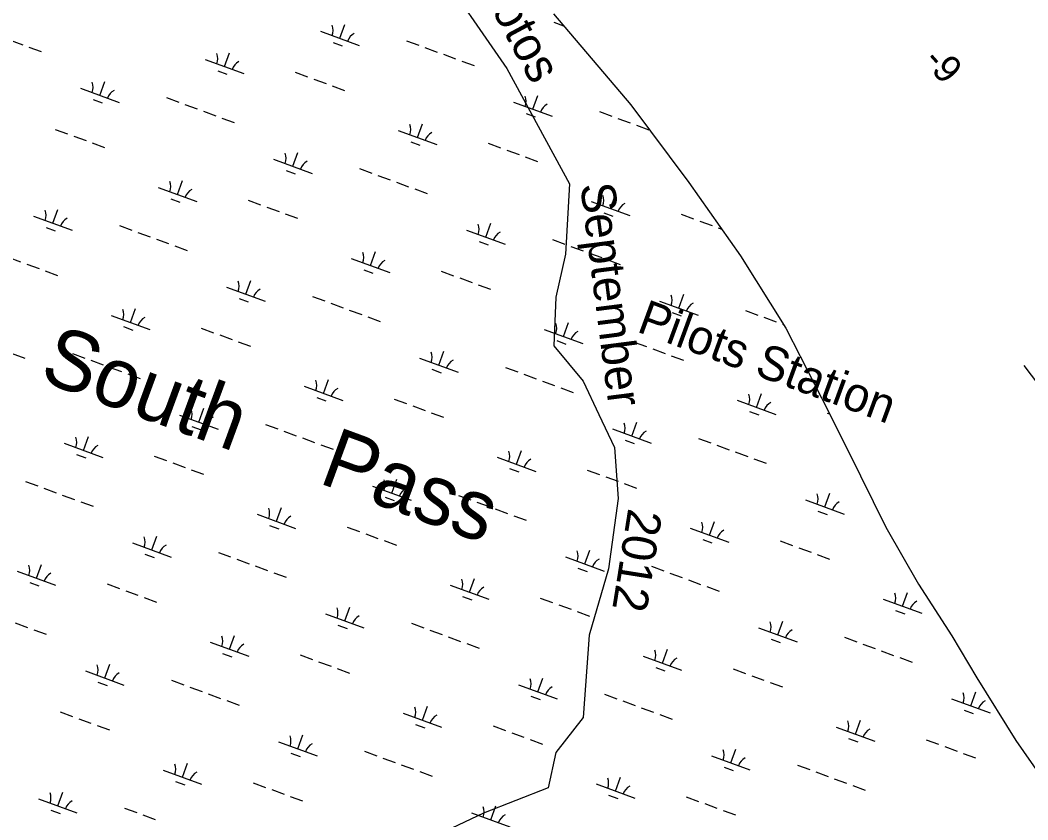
# Model space of a CAD drawing. Extents: x 3972907 to 3994831, y 172639 to 190852.
# Drawn here: x 3980022 to 3981252, y 185903 to 186879 of the extents above; entities that cross this region are included whole.
import ezdxf

# ---------------------------------------------------------------- set-up
doc = ezdxf.new("R2010")
doc.units = 0
for name, color, linetype in [('V-BLDG-IDEN', 7, 'Continuous'), ('V-RIVR-EDGE', 7, 'Continuous'), ('V-RIVR-IDEN', 7, 'Continuous'), ('V-RIVR-JETY', 7, 'Continuous'), ('V-RIVR-RANG', 7, 'Continuous'), ('V-WETL-SWMP', 7, 'Continuous')]:
    doc.layers.add(name, color=color, linetype=linetype)

msp = doc.modelspace()

# ---------------------------------------------------------------- linework, layer by layer
at = {"layer": 'V-RIVR-EDGE'}
msp.add_lwpolyline([(3980525.8, 186951.6), (3980616.4, 186820.4), (3980692.8, 186679.6), (3980688, 186593.7), (3980676.1, 186541.2), (3980673.7, 186481.6), (3980709.5, 186438.6), (3980728.6, 186398.1), (3980747.7, 186357.5), (3980752.4, 186295.5), (3980740.5, 186209.6), (3980716.7, 186128.5), (3980709.5, 186028.3), (3980676.1, 185985.3), (3980666.6, 185942.4), (3980587.8, 185911.3), (3980501.9, 185870.8), (3980444.7, 185844.5), (3980363.5, 185765.8), (3980299.1, 185684.7), (3980222.8, 185605.9), (3980072.4, 185567.8), (3979962.7, 185546.3)], dxfattribs=at)
at = {"layer": 'V-RIVR-JETY'}
msp.add_lwpolyline([(3981247.3, 186457.7), (3981342, 186332.9)], dxfattribs=at)
msp.add_spline([(3980663.7, 188142.5), (3980923.3, 187897.8), (3981219.1, 187593.7), (3981381.5, 187411.2), (3981548.8, 187223.5), (3981746, 186997.4), (3981995.9, 186703.1), (3982288, 186350.3), (3982495.8, 186079.5), (3982762.8, 185654.7), (3982971, 185292.4), (3983111.2, 185037.5), (3983200, 184881.8), (3983229.9, 184826.4)], degree=3, dxfattribs=at)
at = {"layer": 'V-WETL-SWMP'}
for p, q in [((3980412.6, 186857.1), (3980418.8, 186874)), ((3980673.7, 186876.8), (3980685.7, 186872.4)), ((3980389.1, 186865.7), (3980436, 186848.5)), ((3980010.4, 186854.7), (3980025.5, 186849.2)), ((3980404.3, 186851.9), (3980415.5, 186847.8)), ((3980493.9, 186854.2), (3980508.9, 186848.7)), ((3980033, 186846.4), (3980048, 186840.9)), ((3980271.8, 186822.6), (3980278, 186839.5)), ((3980516.4, 186845.9), (3980531.4, 186840.4)), ((3980538.9, 186837.7), (3980553.9, 186832.1)), ((3980248.3, 186831.2), (3980295.2, 186814)), ((3980561.4, 186829.4), (3980576.5, 186823.9)), ((3980263.5, 186817.4), (3980274.8, 186813.3)), ((3980358.2, 186815.6), (3980373.2, 186810)), ((3980119.6, 186787.5), (3980125.8, 186804.4)), ((3980380.7, 186807.3), (3980395.7, 186801.8)), ((3980096.2, 186796.2), (3980143.1, 186778.9)), ((3980403.3, 186799), (3980418.3, 186793.5)), ((3980648.1, 186770.5), (3980654.3, 186787.4)), ((3980111.3, 186782.4), (3980122.6, 186778.2)), ((3980200.9, 186784.7), (3980215.9, 186779.2)), ((3980223.5, 186776.4), (3980238.5, 186770.9)), ((3980624.6, 186779.1), (3980671.6, 186761.9)), ((3980246, 186768.1), (3980261, 186762.6)), ((3980639.8, 186765.3), (3980651.1, 186761.2)), ((3980729.4, 186767.6), (3980744.4, 186762.1)), ((3980268.5, 186759.8), (3980283.5, 186754.3)), ((3980507.3, 186736), (3980513.5, 186752.9)), ((3980751.9, 186759.4), (3980767, 186753.9)), ((3980774.5, 186751.1), (3980789.5, 186745.6)), ((3980065.3, 186746), (3980080.3, 186740.5)), ((3980483.9, 186744.6), (3980530.8, 186727.4)), ((3980087.8, 186737.7), (3980102.8, 186732.2)), ((3980110.3, 186729.5), (3980125.3, 186723.9)), ((3980499, 186730.8), (3980510.3, 186726.7)), ((3980593.7, 186729), (3980608.8, 186723.5)), ((3980355.2, 186701), (3980361.4, 186717.8)), ((3980616.3, 186720.7), (3980631.3, 186715.2)), ((3980331.7, 186709.6), (3980378.6, 186692.3)), ((3980638.8, 186712.4), (3980653.8, 186706.9)), ((3980346.9, 186695.8), (3980358.1, 186691.6)), ((3980436.5, 186698.1), (3980451.5, 186692.6)), ((3980459, 186689.8), (3980474, 186684.3)), ((3980214.4, 186666.5), (3980220.6, 186683.4)), ((3980481.5, 186681.5), (3980496.5, 186676)), ((3980190.9, 186675.1), (3980237.9, 186657.8)), ((3980504.1, 186673.3), (3980519.1, 186667.7)), ((3980742.9, 186649.4), (3980749.1, 186666.3)), ((3980206.1, 186661.3), (3980217.4, 186657.2)), ((3980300.8, 186659.4), (3980315.8, 186653.9)), ((3980719.4, 186658.1), (3980766.3, 186640.8)), ((3980038.8, 186640), (3980085.7, 186622.8)), ((3980062.2, 186631.4), (3980068.5, 186648.3)), ((3980323.3, 186651.2), (3980338.4, 186645.6)), ((3980345.9, 186642.9), (3980360.9, 186637.4)), ((3980734.6, 186644.3), (3980745.8, 186640.1)), ((3980829.3, 186642.4), (3980844.3, 186636.9)), ((3980143.5, 186628.5), (3980158.6, 186623)), ((3980590.7, 186614.4), (3980596.9, 186631.3)), ((3980851.8, 186634.1), (3980866.8, 186628.6)), ((3980054, 186626.2), (3980065.2, 186622.1)), ((3980166.1, 186620.3), (3980181.1, 186614.7)), ((3980567.3, 186623), (3980614.2, 186605.8)), ((3980874.3, 186625.9), (3980878.6, 186624.3)), ((3980188.6, 186612), (3980203.6, 186606.5)), ((3980211.1, 186603.7), (3980226.1, 186598.2)), ((3980582.4, 186609.2), (3980593.7, 186605.1)), ((3980672, 186611.5), (3980687, 186606)), ((3980694.6, 186603.2), (3980709.6, 186597.7)), ((3980449.9, 186579.9), (3980456.2, 186596.8)), ((3980717.1, 186595), (3980732.1, 186589.4)), ((3980007.9, 186589.9), (3980022.9, 186584.4)), ((3980030.4, 186581.6), (3980045.4, 186576.1)), ((3980426.5, 186588.5), (3980473.4, 186571.3)), ((3980739.6, 186586.7), (3980754.6, 186581.2)), ((3980052.9, 186573.3), (3980068, 186567.8)), ((3980441.7, 186574.7), (3980452.9, 186570.6)), ((3980536.4, 186572.9), (3980551.4, 186567.3)), ((3980297.8, 186544.8), (3980304, 186561.7)), ((3980558.9, 186564.6), (3980573.9, 186559.1)), ((3980581.4, 186556.3), (3980596.4, 186550.8)), ((3980274.3, 186553.5), (3980321.3, 186536.2)), ((3980379.1, 186542), (3980394.1, 186536.5)), ((3980826.3, 186527.8), (3980832.5, 186544.7)), ((3980289.5, 186539.7), (3980300.8, 186535.5)), ((3980401.6, 186533.7), (3980416.6, 186528.2)), ((3980802.8, 186536.4), (3980849.7, 186519.2)), ((3980133.6, 186519), (3980180.5, 186501.7)), ((3980157, 186510.3), (3980163.2, 186527.2)), ((3980424.1, 186525.4), (3980439.2, 186519.9)), ((3980446.7, 186517.1), (3980461.7, 186511.6)), ((3980818, 186522.6), (3980829.2, 186518.5)), ((3980907.6, 186524.9), (3980922.6, 186519.4)), ((3980148.7, 186505.2), (3980160, 186501)), ((3980685.5, 186493.3), (3980691.7, 186510.2)), ((3980930.1, 186516.7), (3980945.1, 186511.1)), ((3980952.6, 186508.4), (3980953.8, 186507.9)), ((3980243.4, 186503.3), (3980258.4, 186497.8)), ((3980266, 186495), (3980281, 186489.5)), ((3980662, 186501.9), (3980709, 186484.7)), ((3979981.4, 186483.9), (3980028.3, 186466.7)), ((3980288.5, 186486.8), (3980303.5, 186481.2)), ((3980677.2, 186488.1), (3980688.5, 186484)), ((3980771.9, 186486.3), (3980786.9, 186480.8)), ((3980086.2, 186472.4), (3980101.2, 186466.9)), ((3980533.3, 186458.3), (3980539.5, 186475.1)), ((3980794.4, 186478), (3980809.5, 186472.5)), ((3980817, 186469.7), (3980832, 186464.2)), ((3980108.7, 186464.1), (3980123.7, 186458.6)), ((3980131.2, 186455.9), (3980146.2, 186450.3)), ((3980509.9, 186466.9), (3980556.8, 186449.6)), ((3980614.6, 186455.4), (3980629.7, 186449.9)), ((3980153.7, 186447.6), (3980168.8, 186442.1)), ((3980525, 186453.1), (3980536.3, 186448.9)), ((3980637.2, 186447.1), (3980652.2, 186441.6)), ((3980369.1, 186432.4), (3980416, 186415.1)), ((3980392.6, 186423.8), (3980398.8, 186440.7)), ((3980659.7, 186438.8), (3980674.7, 186433.3)), ((3980384.3, 186418.6), (3980395.5, 186414.5)), ((3980682.2, 186430.6), (3980697.2, 186425)), ((3980921, 186406.7), (3980927.3, 186423.6)), ((3980479, 186416.7), (3980494, 186411.2)), ((3980501.5, 186408.5), (3980516.5, 186402.9)), ((3980897.6, 186415.4), (3980944.5, 186398.1)), ((3980216.9, 186397.3), (3980263.9, 186380.1)), ((3980240.4, 186388.7), (3980246.6, 186405.6)), ((3980524, 186400.2), (3980539, 186394.7)), ((3980912.7, 186401.6), (3980924, 186397.4)), ((3981007.5, 186399.7), (3981010.3, 186398.7)), ((3980232.1, 186383.5), (3980243.4, 186379.4)), ((3980321.7, 186385.8), (3980336.7, 186380.3)), ((3980768.9, 186371.7), (3980775.1, 186388.6)), ((3980099.6, 186354.2), (3980105.8, 186371.1)), ((3980344.2, 186377.6), (3980359.3, 186372)), ((3980366.8, 186369.3), (3980381.8, 186363.8)), ((3980745.4, 186380.3), (3980792.4, 186363.1)), ((3980076.2, 186362.8), (3980123.1, 186345.6)), ((3980389.3, 186361), (3980404.3, 186355.5)), ((3980760.6, 186366.5), (3980771.9, 186362.4)), ((3980850.2, 186368.8), (3980865.2, 186363.3)), ((3980872.7, 186360.5), (3980887.7, 186355)), ((3980091.3, 186349), (3980102.6, 186344.9)), ((3980186, 186347.2), (3980201.1, 186341.7)), ((3980604.6, 186345.8), (3980651.6, 186328.6)), ((3980628.1, 186337.2), (3980634.3, 186354.1)), ((3980895.2, 186352.3), (3980910.3, 186346.7)), ((3980208.6, 186338.9), (3980223.6, 186333.4)), ((3980917.8, 186344), (3980932.8, 186338.5)), ((3980231.1, 186330.6), (3980246.1, 186325.1)), ((3980619.8, 186332), (3980631.1, 186327.9)), ((3980714.5, 186330.2), (3980729.5, 186324.6)), ((3980737.1, 186321.9), (3980752.1, 186316.4)), ((3980028.8, 186316.3), (3980043.8, 186310.8)), ((3980051.3, 186308), (3980066.3, 186302.5)), ((3980452.5, 186310.7), (3980499.4, 186293.5)), ((3980476, 186302.1), (3980482.2, 186319)), ((3980759.6, 186313.6), (3980774.6, 186308.1)), ((3980073.8, 186299.7), (3980088.8, 186294.2)), ((3980467.7, 186297), (3980478.9, 186292.8)), ((3980557.3, 186299.3), (3980572.3, 186293.8)), ((3981004.4, 186285.1), (3981010.6, 186302)), ((3980096.4, 186291.5), (3980111.4, 186285.9)), ((3980335.2, 186267.6), (3980341.4, 186284.5)), ((3980579.8, 186291), (3980594.8, 186285.5)), ((3980981, 186293.7), (3981027.9, 186276.5)), ((3980311.7, 186276.3), (3980358.6, 186259)), ((3980602.3, 186282.7), (3980617.3, 186277.2)), ((3980624.8, 186274.4), (3980639.9, 186268.9)), ((3980996.1, 186279.9), (3981007.4, 186275.8)), ((3980326.9, 186262.5), (3980338.1, 186258.3)), ((3980421.6, 186260.6), (3980436.6, 186255.1)), ((3980840.2, 186259.2), (3980887.1, 186242)), ((3980863.7, 186250.6), (3980869.9, 186267.5)), ((3980183, 186232.6), (3980189.2, 186249.5)), ((3980444.1, 186252.3), (3980459.1, 186246.8)), ((3980159.6, 186241.2), (3980206.5, 186224)), ((3980466.6, 186244.1), (3980481.7, 186238.5)), ((3980855.4, 186245.4), (3980866.6, 186241.3)), ((3980950.1, 186243.6), (3980965.1, 186238.1)), ((3980972.6, 186235.3), (3980987.6, 186229.8)), ((3980174.7, 186227.4), (3980186, 186223.3)), ((3980264.3, 186229.7), (3980279.3, 186224.2)), ((3980688, 186224.2), (3980735, 186206.9)), ((3980711.5, 186215.5), (3980717.7, 186232.4)), ((3980995.1, 186227), (3981010.1, 186221.5)), ((3980042.2, 186198.1), (3980048.5, 186215)), ((3980286.9, 186221.4), (3980301.9, 186215.9)), ((3980309.4, 186213.2), (3980324.4, 186207.6)), ((3980703.2, 186210.4), (3980714.5, 186206.2)), ((3980792.8, 186212.7), (3980807.8, 186207.2)), ((3980018.8, 186206.7), (3980065.7, 186189.5)), ((3980331.9, 186204.9), (3980346.9, 186199.4)), ((3980570.7, 186181.1), (3980576.9, 186198)), ((3980815.3, 186204.4), (3980830.3, 186198.9)), ((3980034, 186192.9), (3980045.2, 186188.8)), ((3980128.7, 186191.1), (3980143.7, 186185.5)), ((3980547.3, 186189.7), (3980594.2, 186172.4)), ((3980837.9, 186196.1), (3980852.9, 186190.6)), ((3980860.4, 186187.9), (3980875.4, 186182.3)), ((3980151.2, 186182.8), (3980166.2, 186177.3)), ((3980173.7, 186174.5), (3980188.7, 186169)), ((3980562.4, 186175.9), (3980573.7, 186171.8)), ((3980657.1, 186174), (3980672.2, 186168.5)), ((3981075.7, 186172.7), (3981122.7, 186155.4)), ((3981099.2, 186164), (3981105.4, 186180.9)), ((3980418.6, 186146), (3980424.8, 186162.9)), ((3980679.7, 186165.8), (3980694.7, 186160.2)), ((3980395.1, 186154.6), (3980442, 186137.4)), ((3980702.2, 186157.5), (3980717.2, 186152)), ((3981090.9, 186158.9), (3981102.2, 186154.7)), ((3980016.4, 186143.6), (3980031.5, 186138.1)), ((3980410.3, 186140.8), (3980421.5, 186136.7)), ((3980499.9, 186143.1), (3980514.9, 186137.6)), ((3980923.6, 186137.6), (3980970.5, 186120.3)), ((3980947, 186129), (3980953.3, 186145.9)), ((3980039, 186135.3), (3980054, 186129.8)), ((3980277.8, 186111.5), (3980284, 186128.4)), ((3980522.4, 186134.9), (3980537.4, 186129.3)), ((3980544.9, 186126.6), (3980559.9, 186121.1)), ((3980938.8, 186123.8), (3980950, 186119.7)), ((3981028.4, 186126.1), (3981043.4, 186120.6)), ((3980254.3, 186120.1), (3980301.3, 186102.9)), ((3980567.5, 186118.3), (3980582.5, 186112.8)), ((3980806.3, 186094.5), (3980812.5, 186111.4)), ((3981050.9, 186117.8), (3981065.9, 186112.3)), ((3980269.5, 186106.3), (3980280.8, 186102.2)), ((3980364.2, 186104.5), (3980379.2, 186099)), ((3980782.8, 186103.1), (3980829.7, 186085.9)), ((3981073.4, 186109.6), (3981088.4, 186104)), ((3981095.9, 186101.3), (3981111, 186095.8)), ((3980125.6, 186076.4), (3980131.8, 186093.3)), ((3980386.7, 186096.2), (3980401.8, 186090.7)), ((3980409.3, 186087.9), (3980424.3, 186082.4)), ((3980798, 186089.3), (3980809.2, 186085.2)), ((3980892.7, 186087.5), (3980907.7, 186081.9)), ((3980102.2, 186085.1), (3980149.1, 186067.8)), ((3980654.1, 186059.4), (3980660.3, 186076.3)), ((3980915.2, 186079.2), (3980930.2, 186073.7)), ((3980117.3, 186071.3), (3980128.6, 186067.1)), ((3980206.9, 186073.6), (3980222, 186068.1)), ((3980229.5, 186065.3), (3980244.5, 186059.8)), ((3980630.7, 186068), (3980677.6, 186050.8)), ((3980937.7, 186070.9), (3980952.8, 186065.4)), ((3980252, 186057), (3980267, 186051.5)), ((3980645.8, 186054.3), (3980657.1, 186050.1)), ((3980735.4, 186056.6), (3980750.4, 186051.1)), ((3981159.1, 186051), (3981206.1, 186033.8)), ((3981182.6, 186042.4), (3981188.8, 186059.3)), ((3980274.5, 186048.8), (3980289.5, 186043.2)), ((3980513.3, 186024.9), (3980519.6, 186041.8)), ((3980757.9, 186048.3), (3980773, 186042.8)), ((3980780.5, 186040), (3980795.5, 186034.5)), ((3981174.3, 186037.2), (3981185.6, 186033.1)), ((3980071.3, 186034.9), (3980086.3, 186029.4)), ((3980093.8, 186026.7), (3980108.8, 186021.1)), ((3980489.9, 186033.6), (3980536.8, 186016.3)), ((3980803, 186031.7), (3980818, 186026.2)), ((3981041.8, 186007.9), (3981048, 186024.8)), ((3980116.3, 186018.4), (3980131.3, 186012.9)), ((3980505, 186019.8), (3980516.3, 186015.6)), ((3980599.8, 186017.9), (3980614.8, 186012.4)), ((3981018.4, 186016.5), (3981065.3, 185999.3)), ((3980361.2, 185989.9), (3980367.4, 186006.8)), ((3980622.3, 186009.6), (3980637.3, 186004.1)), ((3980644.8, 186001.4), (3980659.8, 185995.8)), ((3981033.5, 186002.7), (3981044.8, 185998.6)), ((3981128.2, 186000.9), (3981143.3, 185995.4)), ((3980337.7, 185998.5), (3980384.7, 185981.2)), ((3980889.7, 185972.8), (3980895.9, 185989.7)), ((3981150.8, 185992.6), (3981165.8, 185987.1)), ((3980352.9, 185984.7), (3980364.2, 185980.6)), ((3980442.5, 185987), (3980457.5, 185981.5)), ((3980465, 185978.7), (3980480, 185973.2)), ((3980866.2, 185981.5), (3980913.1, 185964.2)), ((3981173.3, 185984.3), (3981188.3, 185978.8)), ((3980196.9, 185964), (3980243.9, 185946.8)), ((3980220.4, 185955.4), (3980226.6, 185972.3)), ((3980487.5, 185970.5), (3980502.6, 185964.9)), ((3980881.4, 185967.7), (3980892.6, 185963.5)), ((3980971, 185970), (3980986, 185964.5)), ((3980510.1, 185962.2), (3980525.1, 185956.7)), ((3980748.9, 185938.4), (3980755.1, 185955.3)), ((3980993.5, 185961.7), (3981008.5, 185956.2)), ((3981016, 185953.4), (3981031, 185947.9)), ((3980212.1, 185950.2), (3980223.4, 185946.1)), ((3980306.8, 185948.4), (3980321.8, 185942.8)), ((3980329.4, 185940.1), (3980344.4, 185934.6)), ((3980725.4, 185947), (3980772.4, 185929.7)), ((3981038.5, 185945.2), (3981053.6, 185939.6)), ((3980044.8, 185928.9), (3980091.7, 185911.7)), ((3980068.3, 185920.3), (3980074.5, 185937.2)), ((3980351.9, 185931.8), (3980366.9, 185926.3)), ((3980740.6, 185933.2), (3980751.9, 185929.1)), ((3980835.3, 185931.3), (3980850.3, 185925.8)), ((3980060, 185915.2), (3980071.2, 185911)), ((3980149.6, 185917.5), (3980164.6, 185912)), ((3980596.7, 185903.3), (3980602.9, 185920.2)), ((3980857.8, 185923.1), (3980872.8, 185917.5)), ((3980880.4, 185914.8), (3980895.4, 185909.3)), ((3980172.1, 185909.2), (3980187.1, 185903.7)), ((3980573.3, 185911.9), (3980620.2, 185894.7))]:
    msp.add_line(p, q, dxfattribs=at)
msp.add_lwpolyline([(3980673.2, 186887.1), (3980767.5, 186776), (3980838.3, 186681), (3980901.7, 186591.8), (3980956.8, 186503.2), (3981009.2, 186400.9), (3981047.8, 186323.2), (3981078.8, 186260.5), (3981118.6, 186191), (3981159.5, 186127.9), (3981189.9, 186076.4), (3981237.4, 186000.1), (3981299.3, 185911.5)], dxfattribs=at)
for centre, start, end in [((3980386.7, 186866.8), 339.0473, 20.5909), ((3980438.6, 186847.8), 119.0473, 160.5909), ((3980245.9, 186832.3), 339.0473, 20.5909), ((3980297.8, 186813.3), 119.0473, 160.5909), ((3980093.8, 186797.3), 339.0473, 20.5909), ((3980145.6, 186778.2), 119.0473, 160.5909), ((3980622.3, 186780.3), 339.0473, 20.5909), ((3980674.1, 186761.2), 119.0473, 160.5909), ((3980481.5, 186745.8), 339.0473, 20.5909), ((3980533.3, 186726.7), 119.0473, 160.5909), ((3980329.3, 186710.7), 339.0473, 20.5909), ((3980381.2, 186691.6), 119.0473, 160.5909), ((3980188.6, 186676.2), 339.0473, 20.5909), ((3980240.4, 186657.2), 119.0473, 160.5909), ((3980717, 186659.2), 339.0473, 20.5909), ((3980768.9, 186640.1), 119.0473, 160.5909), ((3980036.4, 186641.2), 339.0473, 20.5909), ((3980088.3, 186622.1), 119.0473, 160.5909), ((3980564.9, 186624.1), 339.0473, 20.5909), ((3980616.7, 186605.1), 119.0473, 160.5909), ((3980424.1, 186589.6), 339.0473, 20.5909), ((3980476, 186570.6), 119.0473, 160.5909), ((3980271.9, 186554.6), 339.0473, 20.5909), ((3980323.8, 186535.5), 119.0473, 160.5909), ((3980800.4, 186537.6), 339.0473, 20.5909), ((3980852.3, 186518.5), 119.0473, 160.5909), ((3980131.2, 186520.1), 339.0473, 20.5909), ((3980183, 186501), 119.0473, 160.5909), ((3980659.7, 186503.1), 339.0473, 20.5909), ((3980711.5, 186484), 119.0473, 160.5909), ((3980507.5, 186468), 339.0473, 20.5909), ((3980559.3, 186448.9), 119.0473, 160.5909), ((3980366.7, 186433.5), 339.0473, 20.5909), ((3980418.6, 186414.5), 119.0473, 160.5909), ((3980895.2, 186416.5), 339.0473, 20.5909), ((3980947.1, 186397.4), 119.0473, 160.5909), ((3980214.6, 186398.5), 339.0473, 20.5909), ((3980266.4, 186379.4), 119.0473, 160.5909), ((3980743, 186381.4), 339.0473, 20.5909), ((3980073.8, 186364), 339.0473, 20.5909), ((3980794.9, 186362.4), 119.0473, 160.5909), ((3980125.6, 186344.9), 119.0473, 160.5909), ((3980602.3, 186346.9), 339.0473, 20.5909), ((3980654.1, 186327.9), 119.0473, 160.5909), ((3980450.1, 186311.9), 339.0473, 20.5909), ((3980502, 186292.8), 119.0473, 160.5909), ((3980978.6, 186294.9), 339.0473, 20.5909), ((3980309.3, 186277.4), 339.0473, 20.5909), ((3981030.4, 186275.8), 119.0473, 160.5909), ((3980361.2, 186258.3), 119.0473, 160.5909), ((3980837.8, 186260.4), 339.0473, 20.5909), ((3980157.2, 186242.3), 339.0473, 20.5909), ((3980889.7, 186241.3), 119.0473, 160.5909), ((3980209, 186223.3), 119.0473, 160.5909), ((3980685.7, 186225.3), 339.0473, 20.5909), ((3980737.5, 186206.2), 119.0473, 160.5909), ((3980016.4, 186207.8), 339.0473, 20.5909), ((3980068.3, 186188.8), 119.0473, 160.5909), ((3980544.9, 186190.8), 339.0473, 20.5909), ((3980596.7, 186171.8), 119.0473, 160.5909), ((3981073.4, 186173.8), 339.0473, 20.5909), ((3980392.7, 186155.8), 339.0473, 20.5909), ((3981125.2, 186154.7), 119.0473, 160.5909), ((3980444.6, 186136.7), 119.0473, 160.5909), ((3980921.2, 186138.7), 339.0473, 20.5909), ((3980252, 186121.3), 339.0473, 20.5909), ((3980973.1, 186119.7), 119.0473, 160.5909), ((3980303.8, 186102.2), 119.0473, 160.5909), ((3980780.4, 186104.2), 339.0473, 20.5909), ((3980832.3, 186085.2), 119.0473, 160.5909), ((3980099.8, 186086.2), 339.0473, 20.5909), ((3980151.6, 186067.1), 119.0473, 160.5909), ((3980628.3, 186069.2), 339.0473, 20.5909), ((3980680.1, 186050.1), 119.0473, 160.5909), ((3981156.8, 186052.2), 339.0473, 20.5909), ((3980487.5, 186034.7), 339.0473, 20.5909), ((3981208.6, 186033.1), 119.0473, 160.5909), ((3980539.4, 186015.6), 119.0473, 160.5909), ((3981016, 186017.7), 339.0473, 20.5909), ((3981067.8, 185998.6), 119.0473, 160.5909), ((3980335.3, 185999.6), 339.0473, 20.5909), ((3980387.2, 185980.6), 119.0473, 160.5909), ((3980863.8, 185982.6), 339.0473, 20.5909), ((3980915.7, 185963.5), 119.0473, 160.5909), ((3980194.6, 185965.1), 339.0473, 20.5909), ((3980246.4, 185946.1), 119.0473, 160.5909), ((3980723, 185948.1), 339.0473, 20.5909), ((3980774.9, 185929.1), 119.0473, 160.5909), ((3980042.4, 185930.1), 339.0473, 20.5909), ((3980094.3, 185911), 119.0473, 160.5909), ((3980570.9, 185913), 339.0473, 20.5909), ((3980622.7, 185894), 119.0473, 160.5909)]:
    msp.add_arc(centre, 17.6, start, end, dxfattribs=at)

# ---------------------------------------------------------------- texts
at = {"layer": 'V-BLDG-IDEN'}
msp.add_text('Pilots Station', height=42, rotation=339.819, dxfattribs=at).set_placement((3980773.6, 186499.5))
at = {"layer": 'V-RIVR-IDEN'}
for s, height, rotation, p in [('Aerial Photos', 42, 298.2609, (3980489.3, 187093.4)), ('September ', 42, 277.2977, (3980705.8, 186678.4)), ('South    Pass', 73, 339.819, (3980043.7, 186440.4)), ('2012', 42, 260.9224, (3980764.7, 186284.5))]:
    msp.add_text(s, height=height, rotation=rotation, dxfattribs=at).set_placement(p)
at = {"layer": 'V-RIVR-RANG'}
msp.add_text('-9', height=33.5, rotation=311.9083, dxfattribs=at).set_placement((3981123.4, 186828.8))

doc.saveas('drawing.dxf')
